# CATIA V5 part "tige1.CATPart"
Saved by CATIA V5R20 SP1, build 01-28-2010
Part number: tige1
Bounding box of the stored display mesh (mm): x -12.5 to -7.5, y 80.145 to 773.283, z -49.484 to 92.069
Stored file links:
  C:\Users\Fox\Desktop\IAO Projet\A RENDRE\Sauvegarde IFMA\tige1.CATPart
  C:\Users\Fox\Desktop\IAO Projet\A RENDRE\Sauvegarde IFMA\mpeyrard.CATProduct
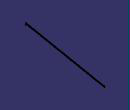
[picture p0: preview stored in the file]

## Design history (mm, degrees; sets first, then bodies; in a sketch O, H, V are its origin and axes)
Set1
  Plane1: linked copy from another document
  Line1: linked copy from another document
  Line2: linked copy from another document
Body1 (main body)
  Sketch1 on Plane1, origin (0, 54.6358, 87.6583), H (-1, 0, 0), V (0, -0.9812, 0.1931)
    axis line L1 (2.5473, -30.4671) -> (19.189, -30.4671)
    reference projected line E1 through (0, 0) direction (0, -1) from Line1
    reference projected point E2 (0, -30.4671) from Line2
    circle A1 centre (10, -30.4671) radius 2.5
    point P3 (10, -30.4671)
    reference projected point E3 (0, -30.4671) from Line2
    distance E2 L1 = 0
    radius A1 = 2.5
    distance P3 E3 = 10
    perpendicularity: E1 L1
    coincidence: P3 L1
  Pad1: profile Sketch1, direction (0, 0.1931, 0.9812), length 10, mirrored extent
  Sketch2 on end face of Pad1, origin (0, 60.1191, 96.771), H (-1, 0, 0), V (0, -0.9812, 0.1931)
    line L1 (7.5, -26.8468) -> (12.5, -26.8468)
    line L2 (12.5, -26.8468) -> (12.5, -726.8468)
    line L3 (12.5, -726.8468) -> (7.5, -726.8468)
    line L4 (7.5, -726.8468) -> (7.5, -26.8468)
    reference projected line E1 through (0, 0) direction (0, -1) from Line1
    reference projected point E2 (0, -26.8468) from Line2
    reference projected line E3 through (0, 0) direction (0, -1) from Line1
    length L3 = 5
    distance L1 E2 = 0
    distance L4 E3 = 7.5
    length L2 = 700
    horizontal: L1 H, L3 H
    vertical: L2 V, L4 V
    parallelism: E1 L4
  Pad2: profile Sketch2, direction (0, -0.1931, -0.9812), length 6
